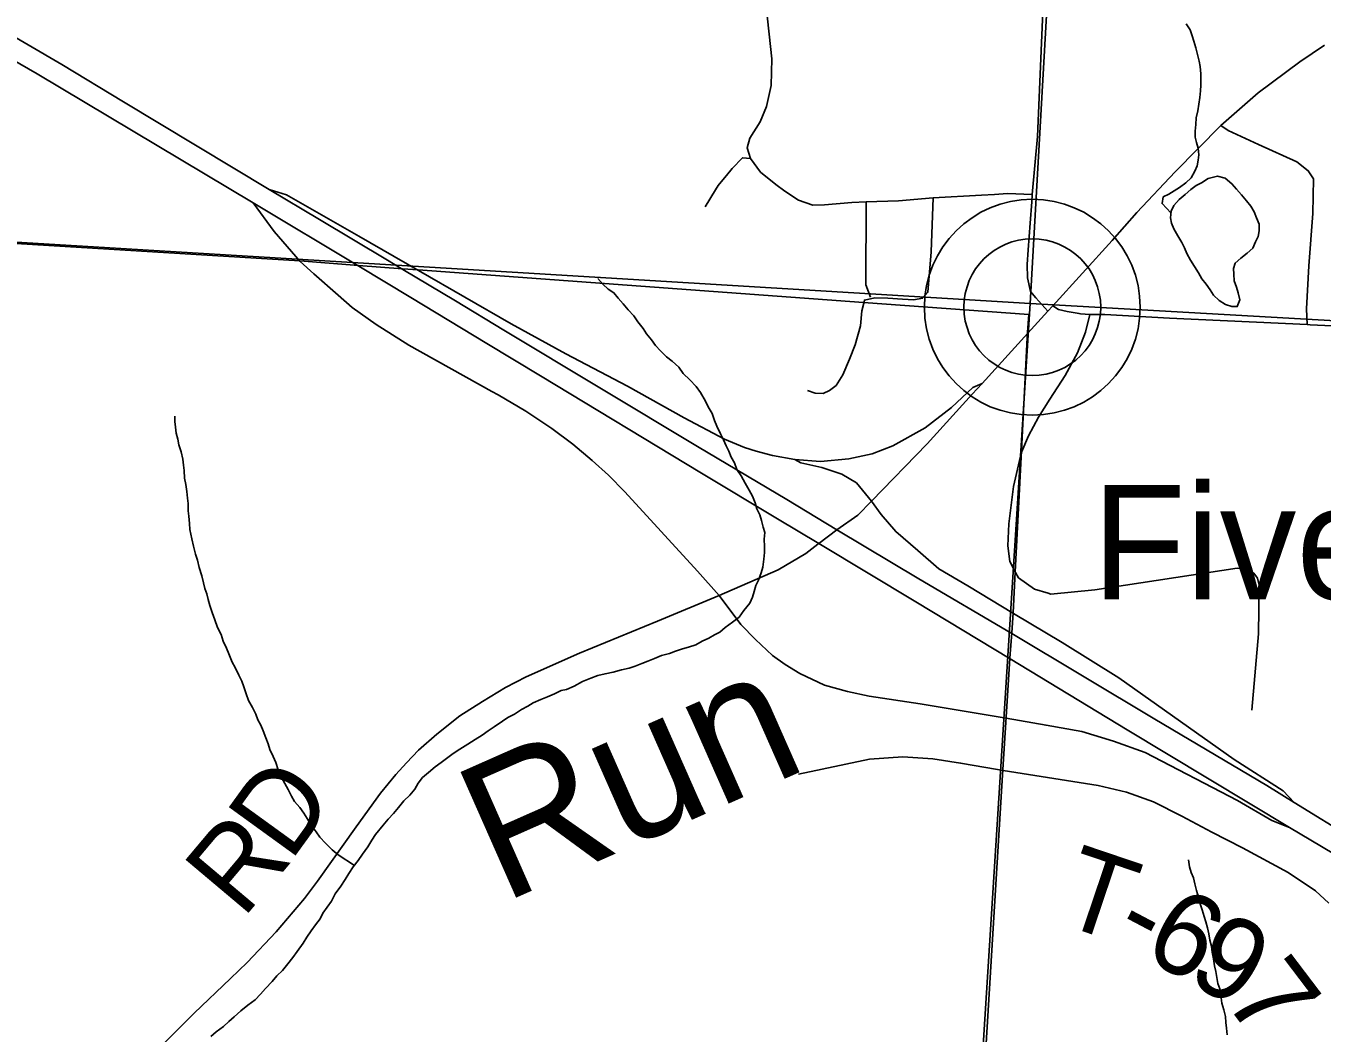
# Model space of a CAD drawing. Extents: x -20.2 to 34, y 0 to 22.
# Drawn here: x 7.17 to 8.064, y 15.377 to 16.071 of the extents above; entities that cross this region are included whole.
import ezdxf

# ---------------------------------------------------------------- set-up
doc = ezdxf.new("R2010")
doc.units = 0
for name, color, linetype in [('Default', 7, 'Continuous'), ('GM_X_County_Road', 7, 'Continuous'), ('GM_X_County_Road_Text', 7, 'Continuous'), ('GM_X_Interchange_Ramps', 7, 'Continuous'), ('GM_X_Minor_River', 7, 'Continuous'), ('GM_X_Minor_River_Text', 7, 'Continuous'), ('GM_X_Section', 7, 'Continuous'), ('GM_X_State_Route', 7, 'Continuous'), ('GM_X_Township_Road', 7, 'Continuous'), ('GM_X_Township_Road_Text', 7, 'Continuous'), ('GM_X_Unincorporated', 7, 'Continuous'), ('GM_X_Unincorporated_Location', 7, 'Continuous'), ('GM_X_Unincorporated_Text', 7, 'Continuous'), ('GM_X_US_Route', 7, 'Continuous')]:
    doc.layers.add(name, color=color, linetype=linetype)

msp = doc.modelspace()

# ---------------------------------------------------------------- linework, layer by layer
at = {"layer": 'Default'}
for points in [[(8.9, 15.82114), (8.9, 16.85373), (7.92004, 16.89751), (7.86237, 15.87982)], [(8.9, 15.37339), (8.9, 15.82114), (7.86237, 15.87982), (7.79854, 14.87534), (8.86966, 14.81913)]]:
    msp.add_lwpolyline(points, close=True, dxfattribs=at)
for points in [[(7.80177, 14.87554), (7.8434, 15.55866), (7.8456, 15.59474), (7.84829, 15.63543), (7.84952, 15.65292), (7.85054, 15.66679), (7.85203, 15.69505), (7.85627, 15.77835), (7.86024, 15.85651), (7.86047, 15.86002), (7.86126, 15.8723), (7.74731, 15.88062), (7.44031, 15.90304), (7.42945, 15.90383), (7.39897, 15.90606), (7.35857, 15.90937), (6.79759, 15.94346)], [(6.79759, 15.94346), (7.35857, 15.90937), (7.39897, 15.90606), (7.42945, 15.90383), (7.44031, 15.90304), (7.74731, 15.88062), (7.86126, 15.8723), (7.86047, 15.86002), (7.86024, 15.85651), (7.85627, 15.77835), (7.85203, 15.69505), (7.85054, 15.66679), (7.84952, 15.65292), (7.84829, 15.63543), (7.8456, 15.59474), (7.8434, 15.55866), (7.80177, 14.87554)]]:
    msp.add_lwpolyline(points, dxfattribs=at)
at = {"layer": 'GM_X_County_Road'}
msp.add_line((7.86231, 15.93518), (7.86091, 15.91684), dxfattribs=at)
for points in [[(7.72235, 16.64406), (7.74979, 16.59622), (7.76587, 16.56877), (7.77842, 16.55348), (7.78325, 16.55004), (7.81138, 16.51861), (7.83946, 16.48482), (7.87425, 16.44084), (7.88306, 16.42755), (7.88916, 16.41449), (7.89115, 16.40679), (7.89348, 16.39432), (7.8919, 16.37374), (7.88742, 16.32081), (7.88295, 16.25992), (7.87649, 16.18239), (7.87077, 16.07553), (7.86729, 15.99502), (7.86365, 15.95491), (7.86343, 15.94985), (7.86231, 15.93518)], [(7.86091, 15.91684), (7.86013, 15.90676), (7.8605, 15.89752)], [(7.8605, 15.89752), (7.86255, 15.88806), (7.86607, 15.88389), (7.87434, 15.87456)], [(7.8778, 15.87836), (7.88173, 15.87577), (7.88784, 15.87443), (7.89597, 15.87289), (7.89704, 15.8728)], [(7.89704, 15.8728), (7.90345, 15.87223), (7.91378, 15.87223), (7.95842, 15.86982), (8.05319, 15.8653), (8.05539, 15.8652), (8.15236, 15.8608), (8.24537, 15.85662), (8.29748, 15.85398), (8.34168, 15.85157), (8.40698, 15.84761), (8.44766, 15.84475), (8.47471, 15.84145), (8.49647, 15.83661), (8.54703, 15.8215), (8.62071, 15.79945), (8.69503, 15.7768), (8.78189, 15.7502), (8.87313, 15.72249), (8.9, 15.71394)]]:
    msp.add_lwpolyline(points, dxfattribs=at)
at = {"layer": 'GM_X_Interchange_Ramps'}
for points in [[(7.82913, 15.82473), (7.8227, 15.82195), (7.80803, 15.80828), (7.78988, 15.79419), (7.76746, 15.7818), (7.75336, 15.77625), (7.73713, 15.77283), (7.7177, 15.77091), (7.69991, 15.77248), (7.6846, 15.77518), (7.67328, 15.77817), (7.66517, 15.78074), (7.6515, 15.78628), (7.6236, 15.80103), (7.58466, 15.82302), (7.54195, 15.84523), (7.50439, 15.86578), (7.44052, 15.90251), (7.39936, 15.92619), (7.34938, 15.95479), (7.33754, 15.95848)], [(7.75289, 15.74371), (7.74247, 15.75639), (7.73244, 15.76216), (7.71855, 15.76685), (7.70416, 15.77017), (7.69991, 15.77248)], [(8.04422, 15.53607), (8.03675, 15.54394), (8.00303, 15.56558), (7.9235, 15.62183), (7.88436, 15.64629), (7.85075, 15.66627), (7.81927, 15.68519), (7.79921, 15.69711), (7.78471, 15.70962), (7.76959, 15.72265), (7.7594, 15.73449), (7.75289, 15.74371)], [(7.64781, 15.67868), (7.66282, 15.65858), (7.67285, 15.64833), (7.6846, 15.63723), (7.69319, 15.63108), (7.70353, 15.62486), (7.72047, 15.61694), (7.73628, 15.61246), (7.75114, 15.60934), (7.78642, 15.60406), (7.84581, 15.59422), (7.87329, 15.58928), (7.89799, 15.58487), (7.91972, 15.57824), (7.94158, 15.57055), (8.00529, 15.53728), (8.02903, 15.52356), (8.04109, 15.51886)]]:
    msp.add_lwpolyline(points, dxfattribs=at)
at = {"layer": 'GM_X_Minor_River'}
for points in [[(7.95932, 15.94243), (7.95328, 15.94879), (7.95401, 15.95335), (7.95779, 15.95528), (7.96157, 15.95758), (7.96535, 15.95989), (7.96951, 15.96296), (7.97328, 15.9664), (7.9759, 15.97098), (7.97739, 15.97479), (7.97813, 15.97859), (7.97848, 15.98239), (7.97807, 15.98694), (7.9769, 15.99073), (7.97611, 15.99452), (7.97608, 15.9987), (7.97643, 16.00326), (7.97677, 16.00782), (7.97788, 16.01277), (7.9786, 16.01733), (7.97933, 16.02189), (7.97967, 16.02645), (7.98003, 16.03025), (7.98, 16.03443), (7.97997, 16.03823), (7.97955, 16.04316), (7.97877, 16.04695), (7.97759, 16.0515), (7.97642, 16.05605), (7.97525, 16.0606), (7.97408, 16.06439), (7.97253, 16.06855), (7.96984, 16.07271)], [(7.98505, 15.9661), (7.98052, 15.96304), (7.97674, 15.96111), (7.97296, 15.95842), (7.96919, 15.95498), (7.96503, 15.95153), (7.96127, 15.94733), (7.9594, 15.94351), (7.95905, 15.93896), (7.95984, 15.93516), (7.96139, 15.93138), (7.96408, 15.92646), (7.96677, 15.92192), (7.9687, 15.91814), (7.97024, 15.91435), (7.97293, 15.90981), (7.97563, 15.90527), (7.97832, 15.90111), (7.98062, 15.89695), (7.98369, 15.89318), (7.98638, 15.8894), (7.98868, 15.88562), (7.99251, 15.88185), (7.99708, 15.87922), (8.00127, 15.87773), (8.00507, 15.87776), (8.00693, 15.88233), (8.00576, 15.88726), (8.00459, 15.89105), (8.00304, 15.89559), (8.00263, 15.90015), (8.0026, 15.90394), (8.00371, 15.90775), (8.00748, 15.9112), (8.01201, 15.91465), (8.01578, 15.91809), (8.01765, 15.92228), (8.01952, 15.92609), (8.02025, 15.9299), (8.02022, 15.93445), (8.01829, 15.939), (8.01674, 15.94316), (8.01443, 15.94695), (8.01137, 15.95072), (8.00792, 15.95487), (8.00447, 15.95865), (8.00141, 15.96242), (7.99682, 15.96619), (7.9915, 15.96759), (7.98505, 15.9661)], [(7.98505, 15.9661), (7.98052, 15.96304), (7.97674, 15.96111), (7.97296, 15.95842), (7.96919, 15.95498), (7.96503, 15.95153), (7.96127, 15.94733), (7.9594, 15.94351), (7.95905, 15.93896), (7.95984, 15.93516), (7.96139, 15.93138), (7.96408, 15.92646), (7.96677, 15.92192), (7.9687, 15.91814), (7.97024, 15.91435), (7.97293, 15.90981), (7.97563, 15.90527), (7.97832, 15.90111), (7.98062, 15.89695), (7.98369, 15.89318), (7.98638, 15.8894), (7.98868, 15.88562), (7.99251, 15.88185), (7.99708, 15.87922), (8.00127, 15.87773)], [(8.00127, 15.87773), (8.00507, 15.87776), (8.00693, 15.88233), (8.00576, 15.88726), (8.00459, 15.89105), (8.00304, 15.89559), (8.00263, 15.90015), (8.0026, 15.90394), (8.00371, 15.90775), (8.00748, 15.9112), (8.01201, 15.91465), (8.01578, 15.91809), (8.01765, 15.92228), (8.01952, 15.92609), (8.02025, 15.9299), (8.02022, 15.93445), (8.01829, 15.939), (8.01674, 15.94316), (8.01443, 15.94695), (8.01137, 15.95072), (8.00792, 15.95487), (8.00447, 15.95865), (8.00141, 15.96242), (7.99682, 15.96619), (7.9915, 15.96759), (7.98505, 15.9661)], [(7.56407, 15.89702), (7.56752, 15.89325), (7.57134, 15.88986), (7.57515, 15.88723), (7.57822, 15.88345), (7.58167, 15.87968), (7.58511, 15.87553), (7.58894, 15.87138), (7.59163, 15.86722), (7.59546, 15.86269), (7.59777, 15.8589), (7.60121, 15.85475), (7.6039, 15.85097), (7.60735, 15.8472), (7.61155, 15.84305), (7.61537, 15.84004), (7.61996, 15.8359), (7.62303, 15.83174), (7.62762, 15.82721), (7.63183, 15.82269), (7.63489, 15.81853), (7.63836, 15.81248), (7.64028, 15.8087), (7.64297, 15.80416), (7.64453, 15.79923), (7.64608, 15.79544), (7.64877, 15.79015), (7.6507, 15.78598), (7.65263, 15.78182), (7.65456, 15.77803), (7.65611, 15.77387), (7.65841, 15.77009), (7.65996, 15.76554), (7.66304, 15.761), (7.66573, 15.75609), (7.66842, 15.75117), (7.67073, 15.74701), (7.67267, 15.74246), (7.67383, 15.73829), (7.67576, 15.73413), (7.67693, 15.73034), (7.6781, 15.72579), (7.67927, 15.722), (7.67892, 15.71744), (7.67896, 15.7125), (7.67899, 15.70833), (7.67864, 15.70376), (7.67793, 15.69806), (7.67682, 15.69426), (7.67496, 15.68931), (7.67308, 15.68549), (7.67198, 15.68131), (7.67086, 15.6775), (7.669, 15.67331), (7.66486, 15.66834), (7.66147, 15.66376), (7.65694, 15.66031), (7.65203, 15.65648), (7.64826, 15.65341), (7.64448, 15.65149), (7.6407, 15.64918), (7.63615, 15.64725), (7.63162, 15.64456), (7.62669, 15.643), (7.62252, 15.64184), (7.6176, 15.64028), (7.61343, 15.63873), (7.60813, 15.63718), (7.60321, 15.63524), (7.59866, 15.63331), (7.5945, 15.63176), (7.58996, 15.62983), (7.58579, 15.62866), (7.58048, 15.62748), (7.57479, 15.62592), (7.56911, 15.62474), (7.56418, 15.62357), (7.55926, 15.62164), (7.55358, 15.61932), (7.5479, 15.61624), (7.54261, 15.61392), (7.53882, 15.61313), (7.53428, 15.61082), (7.52935, 15.60889), (7.52481, 15.60696), (7.51951, 15.60464), (7.51573, 15.60233), (7.51157, 15.60002), (7.50666, 15.59695), (7.50212, 15.59464), (7.49834, 15.59195), (7.49267, 15.58812), (7.48852, 15.58543), (7.48436, 15.58236), (7.47945, 15.57929), (7.47453, 15.57621), (7.46886, 15.57275), (7.46433, 15.56968), (7.4598, 15.56623), (7.45602, 15.56354), (7.45187, 15.56048)], [(7.27238, 15.80228), (7.27241, 15.79848), (7.27282, 15.79468), (7.27323, 15.79051), (7.27439, 15.78634), (7.27518, 15.78255), (7.27674, 15.77762), (7.27791, 15.77269), (7.27832, 15.76852), (7.27873, 15.76472), (7.27915, 15.75941), (7.27994, 15.75523), (7.28073, 15.7503), (7.28115, 15.74575), (7.28156, 15.74195), (7.28159, 15.73702), (7.282, 15.73322), (7.28242, 15.72829), (7.28283, 15.72411), (7.28401, 15.71766), (7.28519, 15.71274), (7.28675, 15.70705), (7.28792, 15.70288), (7.28909, 15.69795), (7.29103, 15.69227), (7.29221, 15.68734), (7.293, 15.68354), (7.29454, 15.67976), (7.29533, 15.67597), (7.2965, 15.6718), (7.29806, 15.66687), (7.29999, 15.66195), (7.30193, 15.65664), (7.30424, 15.65172), (7.3058, 15.64718), (7.30811, 15.64225), (7.30966, 15.63846), (7.31198, 15.63279), (7.3139, 15.629), (7.3166, 15.6237), (7.31853, 15.61954), (7.32008, 15.61575), (7.32163, 15.61082), (7.32318, 15.60628), (7.32588, 15.60136), (7.32819, 15.59682), (7.32974, 15.59303), (7.33166, 15.58925), (7.33321, 15.58546), (7.33514, 15.58054), (7.33669, 15.57637), (7.33786, 15.57258), (7.34017, 15.56766), (7.3421, 15.56349), (7.34366, 15.55857), (7.34598, 15.55327), (7.34829, 15.5491), (7.3506, 15.54494), (7.35291, 15.5404), (7.35483, 15.53661), (7.35866, 15.53246), (7.36135, 15.52868), (7.36365, 15.5249), (7.36635, 15.52036), (7.3698, 15.51583), (7.37248, 15.51205), (7.37631, 15.5079), (7.3809, 15.50338), (7.3851, 15.49999), (7.39619, 15.49266)], [(7.45187, 15.56048), (7.44734, 15.55665), (7.44319, 15.5532), (7.44018, 15.54938), (7.43793, 15.54518), (7.43454, 15.54098), (7.43039, 15.53715), (7.42663, 15.53257), (7.42324, 15.52837), (7.41948, 15.52454), (7.41609, 15.52034), (7.41082, 15.51385), (7.40819, 15.51003), (7.40557, 15.50545), (7.40181, 15.50049), (7.3988, 15.49591), (7.39542, 15.49171), (7.39241, 15.48712), (7.38978, 15.48293), (7.38678, 15.47835), (7.38302, 15.473), (7.3804, 15.46805), (7.37739, 15.46385), (7.37439, 15.45965), (7.37252, 15.45583), (7.36951, 15.45164), (7.3665, 15.44744), (7.36349, 15.44324), (7.36087, 15.43904), (7.35673, 15.43331), (7.35373, 15.42911), (7.35034, 15.42491), (7.34658, 15.42032), (7.34281, 15.4165), (7.33942, 15.41268), (7.3349, 15.40771), (7.33151, 15.40388), (7.32774, 15.40006), (7.32283, 15.39622), (7.31792, 15.39239), (7.3134, 15.38818), (7.30963, 15.38511), (7.30585, 15.38167), (7.30095, 15.37783), (7.29717, 15.37477)], [(7.97142, 15.49657), (7.97221, 15.49163), (7.97338, 15.48784), (7.97493, 15.48406), (7.97572, 15.47988), (7.97689, 15.47533), (7.97844, 15.47079), (7.97961, 15.46624), (7.98078, 15.46207), (7.98234, 15.45752), (7.9835, 15.45373), (7.98467, 15.44956), (7.98546, 15.44539), (7.98626, 15.44121), (7.98742, 15.43704), (7.98784, 15.43287), (7.98863, 15.42832), (7.98942, 15.42338), (7.99021, 15.41959), (7.991, 15.41542), (7.99179, 15.41125), (7.99296, 15.40746), (7.99375, 15.40328), (7.99455, 15.39759), (7.99572, 15.39304), (7.9969, 15.38849), (7.99731, 15.38432), (7.99772, 15.38052), (7.99813, 15.37596)]]:
    msp.add_lwpolyline(points, dxfattribs=at)
at = {"layer": 'GM_X_Section'}
for points in [[(6.85272, 16.95336), (7.92004, 16.89751), (7.86237, 15.87982), (6.79044, 15.94473), (6.80008, 16.11433), (6.82053, 16.44033)], [(6.79044, 15.94473), (7.86237, 15.87982), (7.79854, 14.87534), (6.72741, 14.93458), (6.77473, 15.69297)]]:
    msp.add_lwpolyline(points, close=True, dxfattribs=at)
at = {"layer": 'GM_X_State_Route'}
for points in [[(6.41816, 16.10902), (6.45434, 16.11988), (6.49273, 16.13059), (6.52435, 16.13942), (6.58094, 16.15154), (6.6469, 16.16005), (6.69286, 16.16322), (6.72265, 16.1641), (6.76329, 16.16346), (6.80371, 16.16069), (6.84945, 16.1558), (6.90222, 16.14644), (6.95945, 16.13261), (7.01817, 16.11431), (7.06349, 16.09644), (7.08985, 16.08496), (7.1337, 16.06325), (7.17753, 16.03814), (7.32636, 15.9492)], [(7.87434, 15.87456), (7.8778, 15.87836), (7.91879, 15.92324), (7.93577, 15.9426), (7.96216, 15.97052), (7.99382, 16.00262), (8.01955, 16.02505), (8.04835, 16.04638), (8.06529, 16.05782)], [(7.32636, 15.9492), (7.34083, 15.92947), (7.35878, 15.90885), (7.36817, 15.90027), (7.38498, 15.88559), (7.39474, 15.87723), (7.41114, 15.86538), (7.4337, 15.85112), (7.49098, 15.81927)], [(7.82236, 15.81732), (7.82913, 15.82473), (7.86067, 15.8595), (7.87434, 15.87456)], [(7.49098, 15.81927), (7.49539, 15.81682), (7.5144, 15.80572), (7.53234, 15.79376), (7.54686, 15.78287), (7.5601, 15.77176), (7.57141, 15.76152), (7.58274, 15.74998), (7.63292, 15.69532), (7.64781, 15.67868)], [(7.7158, 15.71392), (7.71655, 15.71449), (7.72904, 15.72386), (7.7434, 15.73395), (7.75289, 15.74371), (7.79122, 15.7832), (7.82236, 15.81732)], [(7.64781, 15.67868), (7.68852, 15.69644), (7.70748, 15.70769), (7.7158, 15.71392)], [(7.15291, 15.26065), (7.19678, 15.30288), (7.23818, 15.34303), (7.28563, 15.39079), (7.31078, 15.4148), (7.32222, 15.42562), (7.34219, 15.44684), (7.36175, 15.46993), (7.3709, 15.48179), (7.39752, 15.51923), (7.41417, 15.54253), (7.42478, 15.55522), (7.43206, 15.56334), (7.44048, 15.57215), (7.45307, 15.5831), (7.46888, 15.59578), (7.48448, 15.60557), (7.5005, 15.61534), (7.51467, 15.62258), (7.55146, 15.63883), (7.60523, 15.66091), (7.64781, 15.67868)]]:
    msp.add_lwpolyline(points, dxfattribs=at)
at = {"layer": 'GM_X_Township_Road'}
for p, q in [((7.65373, 15.96919), (7.65593, 15.97184)), ((7.63817, 15.94656), (7.64533, 15.95829))]:
    msp.add_line(p, q, dxfattribs=at)
for points in [[(7.86365, 15.95491), (7.84666, 15.95575), (7.83772, 15.95501), (7.82878, 15.95451), (7.79546, 15.95276), (7.77144, 15.95058), (7.74928, 15.95005), (7.73931, 15.94954), (7.72043, 15.9478), (7.7123, 15.94773), (7.70254, 15.95103), (7.69309, 15.95725), (7.68688, 15.96197), (7.6762, 15.97042), (7.66949, 15.97986), (7.667, 15.98707), (7.66899, 15.99378), (7.67595, 16.00496), (7.6804, 16.01569), (7.68365, 16.03006), (7.68415, 16.04845), (7.68018, 16.0845)], [(7.99382, 16.00262), (7.99888, 15.9991), (8.01973, 15.98953), (8.04615, 15.97755), (8.05407, 15.9714), (8.05759, 15.9659), (8.05715, 15.94194), (8.05451, 15.90587), (8.05291, 15.87624), (8.05319, 15.8653)], [(7.65593, 15.97184), (7.65681, 15.9729), (7.66377, 15.98036), (7.66949, 15.97986)], [(7.64533, 15.95829), (7.64712, 15.96122), (7.65373, 15.96919)], [(7.79546, 15.95276), (7.79399, 15.9155), (7.79175, 15.88767), (7.78802, 15.88344), (7.78206, 15.88245), (7.77411, 15.88294), (7.76416, 15.88344), (7.75522, 15.88369), (7.74801, 15.8822), (7.74752, 15.88009), (7.74627, 15.87474), (7.74528, 15.86455), (7.74155, 15.85139), (7.73757, 15.84144), (7.7331, 15.83076), (7.72838, 15.82331), (7.72391, 15.81983), (7.71944, 15.81784), (7.71397, 15.81809), (7.70875, 15.81983)], [(7.75224, 15.88419), (7.74901, 15.89264), (7.74928, 15.95005)], [(7.86805, 15.80143), (7.87574, 15.81397), (7.8863, 15.83023), (7.89501, 15.8459), (7.90037, 15.86014), (7.90345, 15.87223)], [(7.8555, 15.7746), (7.85596, 15.77658), (7.85647, 15.77782), (7.86101, 15.78868), (7.86805, 15.80143)], [(7.87472, 15.68016), (7.86519, 15.68291), (7.8542, 15.69083), (7.85224, 15.69453), (7.84826, 15.70205), (7.84694, 15.71282), (7.8476, 15.72799), (7.85068, 15.75372), (7.8555, 15.7746)], [(8.01515, 15.59958), (8.01977, 15.65213), (8.02016, 15.68583), (8.01901, 15.69066), (8.01649, 15.69414), (8.01205, 15.69665), (8.00509, 15.69743), (7.90676, 15.6826), (7.87663, 15.67961), (7.87472, 15.68016)], [(7.70254, 15.5555), (7.75156, 15.56596), (7.77444, 15.56748), (7.79514, 15.56618), (7.81431, 15.56313), (7.8397, 15.5588)], [(7.8397, 15.5588), (7.84361, 15.55814), (7.90909, 15.54765), (7.9287, 15.54308), (7.94743, 15.53654), (7.96682, 15.52652), (7.98752, 15.51563), (8.00865, 15.50474), (8.04025, 15.48774), (8.05898, 15.4751), (8.06835, 15.46661)]]:
    msp.add_lwpolyline(points, dxfattribs=at)
at = {"layer": 'GM_X_Unincorporated'}
for radius in [0.0744, 0.04716]:
    msp.add_circle((7.86375, 15.87731), radius, dxfattribs=at)
at = {"layer": 'GM_X_Unincorporated_Location'}
msp.add_line((7.86375, 15.87731), (7.86375, 15.87731), dxfattribs=at)
at = {"layer": 'GM_X_US_Route'}
msp.add_line((7.48759, 15.85233), (7.52459, 15.83001), dxfattribs=at)
for points in [[(6.41615, 16.12258), (6.45447, 16.13315), (6.55116, 16.15984), (6.58201, 16.16559), (6.62691, 16.17239), (6.67116, 16.17601), (6.72329, 16.17814), (6.76158, 16.1775), (6.81073, 16.17409), (6.85988, 16.16835), (6.89392, 16.1626), (6.94541, 16.1509), (6.98987, 16.13835), (7.02647, 16.12601), (7.07902, 16.10538), (7.12264, 16.08495), (7.15051, 16.07006), (7.19455, 16.04453), (7.23689, 16.01878), (7.33754, 15.95848)], [(6.41816, 16.10902), (6.45434, 16.11988), (6.49273, 16.13059), (6.52435, 16.13942), (6.58094, 16.15154), (6.6469, 16.16005), (6.69286, 16.16322), (6.72265, 16.1641), (6.76329, 16.16346), (6.80371, 16.16069), (6.84945, 16.1558), (6.90222, 16.14644), (6.95945, 16.13261), (7.01817, 16.11431), (7.06349, 16.09644), (7.08985, 16.08496), (7.1337, 16.06325), (7.17753, 16.03814), (7.32636, 15.9492)], [(7.33754, 15.95848), (7.37221, 15.93772), (7.41902, 15.90963), (7.42966, 15.90331), (7.46592, 15.88175), (7.49924, 15.86146), (7.63292, 15.78138), (7.69442, 15.74486), (7.72904, 15.72386), (7.7854, 15.69019), (7.84973, 15.6524), (7.94826, 15.59347), (8.02544, 15.5476), (8.04422, 15.53607)], [(7.32636, 15.9492), (7.39918, 15.90553), (7.4351, 15.88399), (7.48759, 15.85233)], [(7.52459, 15.83001), (7.6356, 15.76305), (7.68813, 15.73154)], [(7.68813, 15.73154), (7.71655, 15.71449), (7.78344, 15.67436), (7.8485, 15.63491), (7.92914, 15.586), (8.04109, 15.51886)], [(8.04422, 15.53607), (8.08541, 15.51078), (8.13987, 15.47903), (8.18155, 15.45125), (8.24045, 15.40847), (8.24834, 15.39861)], [(8.04109, 15.51886), (8.1696, 15.44244), (8.22945, 15.40641)]]:
    msp.add_lwpolyline(points, dxfattribs=at)

# ---------------------------------------------------------------- texts
at = {"layer": 'GM_X_County_Road_Text'}
for s, rotation, p in [('D', 54.10643, (7.35202, 15.4944)), ('R', 49.92407, (7.31924, 15.45518))]:
    msp.add_text(s, height=0.05682, rotation=rotation, dxfattribs=at).set_placement(p)
at = {"layer": 'GM_X_Minor_River_Text'}
msp.add_text('Run', height=0.094696, rotation=23.85886, dxfattribs=at).set_placement((7.49826, 15.46619))
at = {"layer": 'GM_X_Township_Road_Text'}
for s, rotation, p in [('T', 341.33331, (7.87952, 15.45362)), ('6', 331.99425, (7.93818, 15.4301)), ('-', 332.18511, (7.91759, 15.44097)), ('9', 330.50363, (7.96874, 15.41386)), ('7', 307.2113, (7.99464, 15.40061))]:
    msp.add_text(s, height=0.05682, rotation=rotation, dxfattribs=at).set_placement(p)
at = {"layer": 'GM_X_Unincorporated_Text'}
msp.add_text('Five Points', height=0.0789773, rotation=0.00001, dxfattribs=at).set_placement((7.905, 15.67589))

doc.saveas('drawing.dxf')
